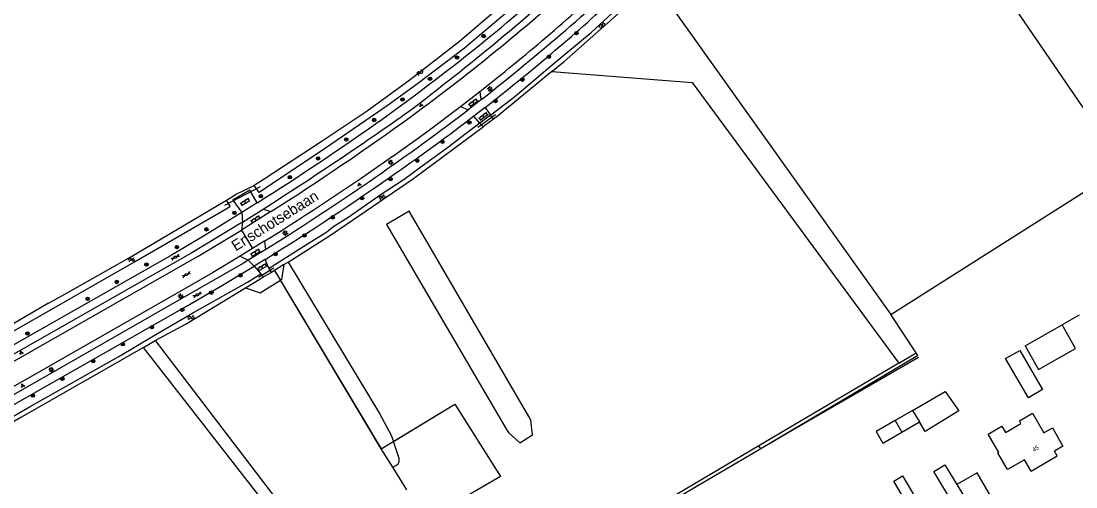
# Model space of a CAD drawing. Extents: x 135999 to 138000, y 396000 to 398501.
# Drawn here: x 136302.3 to 136547.8, y 397723.2 to 397831.7 of the extents above; entities that cross this region are included whole.
import ezdxf

# ---------------------------------------------------------------- set-up
doc = ezdxf.new("R2010")
doc.units = 0
for name, color, linetype in [('gg-afsc-lijn draadraster', 7, 'Continuous'), ('gg-afsc-muur', 7, 'Continuous'), ('gg-anno-huisnummerreeks BGT', 7, 'Continuous'), ('gg-anno-openbare ruimte label', 7, 'Continuous'), ('gg-bbg-bijgebouw', 7, 'Continuous'), ('gg-bbg-gedigitaliseerde bebouwing', 7, 'Continuous'), ('gg-bbg-gedigitaliseerde bijgebouw', 7, 'Continuous'), ('gg-bbg-hoofdgebouw', 7, 'Continuous'), ('gg-bbg-tussenscheiding', 7, 'Continuous'), ('gg-knt-verharding', 7, 'Continuous'), ('gg-kntw-bovenkant insteek waterloop', 7, 'Continuous'), ('gg-kwrk-duiker nz buis', 7, 'Continuous'), ('gt-grn-groengrens', 7, 'Continuous'), ('gt-grn-vlakafsluiter', 7, 'Continuous'), ('gt-grn-weggrens', 7, 'Continuous'), ('gt-symb-boom', 7, 'Continuous'), ('gt-symb-gesloten verharding', 7, 'Continuous'), ('gt-symb-groenvak', 7, 'Continuous'), ('gt-symb-klinker verharding', 7, 'Continuous'), ('gt-symb-lichtmast', 7, 'Continuous'), ('gt-symb-watersymbool', 7, 'Continuous'), ('gx-grn-maaiveld', 7, 'Continuous')]:
    doc.layers.add(name, color=color, linetype=linetype)

# ---------------------------------------------------------------- blocks, each defined once
blk = doc.blocks.new('gt0-BOOM')
at = {"layer": 'gt-symb-boom'}
for radius in [0.4, 0.2]:
    blk.add_circle((0, 0), radius, dxfattribs=at)
blk = doc.blocks.new('gt0-WA')
at = {"layer": 'gt-symb-watersymbool'}
for centre, start, end in [((-0.32, 0.02), 28.0725, 151.9275), ((0.43, 0.42), 208.0725, 331.9275), ((-0.32, -0.43), 28.0725, 151.9275), ((0.43, -0.03), 208.0725, 331.9275)]:
    blk.add_arc(centre, 0.425, start, end, dxfattribs=at)
blk = doc.blocks.new('gt0-GRVAK')
at = {"layer": 'gt-symb-groenvak'}
for p, q in [((-0.11, 0.19), (-0.23, 0.24)), ((-0.18, 0.15), (0.09, 0.15)), ((-0.09, 0.21), (-0.16, 0.32)), ((-0.05, 0.21), (-0.05, 0.39)), ((0, 0.21), (0.06, 0.32)), ((0.02, 0.19), (0.13, 0.24)), ((0.26, -0.05), (0.2, 0.06)), ((0.3, -0.05), (0.3, 0.13)), ((0.35, -0.05), (0.41, 0.06)), ((-0.24, -0.23), (-0.36, -0.18)), ((-0.32, -0.26), (-0.05, -0.26)), ((-0.23, -0.21), (-0.29, -0.1)), ((-0.18, -0.2), (-0.18, -0.02)), ((-0.14, -0.21), (-0.07, -0.1)), ((-0.12, -0.23), (0, -0.18)), ((0.24, -0.07), (0.12, -0.02)), ((0.17, -0.11), (0.44, -0.11)), ((0.37, -0.07), (0.49, -0.02))]:
    blk.add_line(p, q, dxfattribs=at)
blk = doc.blocks.new('gt0-LMAST')
at = {"layer": 'gt-symb-lichtmast'}
for p, q in [((-0.18, 0.17), (-0.45, 0.44)), ((-0.01, 0.25), (-0.01, 0.62)), ((0.17, 0.17), (0.44, 0.44)), ((-0.26, 0), (-0.63, 0)), ((-0.18, -0.18), (-0.45, -0.45)), ((-0.01, -0.25), (-0.01, -0.63)), ((0.44, -0.45), (0.17, -0.18)), ((0.24, 0), (0.62, 0))]:
    blk.add_line(p, q, dxfattribs=at)
blk.add_circle((-0.01, 0), 0.25, dxfattribs=at)
blk = doc.blocks.new('gt0-KL1')
at = {"layer": 'gt-symb-klinker verharding'}
for p, q in [((-1.15, 0.3), (1.15, 0.3)), ((-1, -0.3), (-1, 0.3)), ((-0.5, 0.3), (-0.5, 0.45)), ((0, -0.3), (0, 0.3)), ((0.5, 0.3), (0.5, 0.45)), ((1, -0.3), (1, 0.3)), ((-1.15, -0.3), (1.15, -0.3)), ((-0.5, -0.45), (-0.5, -0.3)), ((0.5, -0.45), (0.5, -0.3))]:
    blk.add_line(p, q, dxfattribs=at)
blk = doc.blocks.new('gt0-GESVH1')
at = {"layer": 'gt-symb-gesloten verharding'}
for p, q in [((-0.99, -0.26), (0.01, 0.24)), ((0.01, -0.26), (-0.99, 0.24)), ((0.01, 0.24), (1.01, -0.26)), ((1.01, 0.24), (0.01, -0.26))]:
    blk.add_line(p, q, dxfattribs=at)

msp = doc.modelspace()

# ---------------------------------------------------------------- linework, layer by layer
at = {"layer": 'gg-afsc-lijn draadraster'}
for points in [[(136361.32, 397773.58), (136386.13, 397732.1), (136403.25, 397742.5), (136413.87, 397725.66), (136396.47, 397715.47), (136406.27, 397699.96)], [(136406.27, 397699.96), (136406.51, 397699.57), (136408.1, 397698.31), (136433.71, 397714.55), (136438.11, 397713.96), (136442.5, 397713.38), (136481.62, 397736.34), (136511.13, 397753.39)]]:
    msp.add_lwpolyline(points, dxfattribs=at)
at = {"layer": 'gg-afsc-muur'}
msp.add_line((136548.54, 397763.19), (136544.57, 397760.93), dxfattribs=at)
at = {"layer": 'gg-bbg-bijgebouw'}
msp.add_line((136535.95, 397756.03), (136544.57, 397760.93), dxfattribs=at)
at = {"layer": 'gg-bbg-gedigitaliseerde bebouwing'}
msp.add_line((136524.79, 397726.5), (136520.05, 397723.74), dxfattribs=at)
for points in [[(136520.73, 397716.72), (136514.72, 397726.81), (136517.3, 397728.34), (136520.05, 397723.74)], [(136509.82, 397716.95), (136505.37, 397724.54), (136507.43, 397725.76), (136510.21, 397721.05)]]:
    msp.add_lwpolyline(points, dxfattribs=at)
at = {"layer": 'gg-bbg-gedigitaliseerde bijgebouw'}
for p, q in [((136509.74, 397741.03), (136505.68, 397738.68)), ((136507.25, 397735.96), (136511.35, 397738.34))]:
    msp.add_line(p, q, dxfattribs=at)
for points in [[(136535.95, 397756.03), (136539.09, 397750.52), (136547.71, 397755.43), (136544.57, 397760.93)], [(136531.42, 397753.08), (136534.74, 397755), (136540.02, 397745.88), (136536.7, 397743.96), (136531.42, 397753.08)], [(136509.74, 397741.03), (136517.36, 397745.45), (136520.52, 397740.94), (136512.68, 397736.1), (136511.35, 397738.34)], [(136505.68, 397738.68), (136501.3, 397736.14), (136502.88, 397733.43), (136507.25, 397735.96)]]:
    msp.add_lwpolyline(points, dxfattribs=at)
at = {"layer": 'gg-bbg-hoofdgebouw'}
msp.add_line((136544.75, 397732.71), (136542.76, 397731.56), dxfattribs=at)
for points in [[(136537.33, 397726.92), (136535.81, 397729.55), (136531.89, 397727.26), (136529.63, 397731.14), (136529.81, 397731.24), (136527.32, 397735.5), (136530.52, 397737.35), (136531.37, 397735.89), (136534.98, 397737.98), (136534.61, 397738.62), (136537.65, 397740.38), (136540.3, 397735.8), (136542.29, 397736.95), (136544.75, 397732.71)], [(136537.33, 397726.92), (136543.41, 397730.43), (136542.76, 397731.56)], [(136527.5, 397711.42), (136532.02, 397714.07), (136524.79, 397726.5)]]:
    msp.add_lwpolyline(points, dxfattribs=at)
at = {"layer": 'gg-bbg-tussenscheiding'}
for p, q in [((136509.74, 397741.03), (136511.35, 397738.34)), ((136505.68, 397738.68), (136507.25, 397735.96))]:
    msp.add_line(p, q, dxfattribs=at)
msp.add_lwpolyline([(136520.05, 397723.74), (136523.37, 397718.29), (136527.5, 397711.42)], dxfattribs=at)
at = {"layer": 'gg-knt-verharding'}
for p, q in [((136404.58, 397811.81), (136409.08, 397815.3)), ((136404.58, 397811.81), (136406.39, 397811.02)), ((136409.52, 397813.46), (136406.39, 397811.02)), ((136410.32, 397811.57), (136407.72, 397809.56)), ((136410.32, 397811.57), (136411.59, 397809.76)), ((136404.03, 397809.21), (136406.39, 397811.02)), ((136409.1, 397807.89), (136407.72, 397809.56)), ((136411.59, 397809.76), (136409.1, 397807.89)), ((136357.26, 397789.32), (136353.67, 397787.08)), ((136360.49, 397787.31), (136353.62, 397783.01)), ((136353.83, 397784.87), (136358.67, 397787.91)), ((136358.67, 397787.91), (136360.49, 397787.31)), ((136353.83, 397784.87), (136353.62, 397783.01)), ((136359.08, 397780.49), (136356.21, 397778.73)), ((136359.27, 397778.52), (136359.08, 397780.49)), ((136356.21, 397778.73), (136353.34, 397776.96)), ((136359.27, 397778.52), (136355.21, 397776.01)), ((136353.34, 397776.96), (136355.21, 397776.01)), ((136359.14, 397776.18), (136356.58, 397774.6)), ((136356.58, 397774.6), (136358.09, 397772.84))]:
    msp.add_line(p, q, dxfattribs=at)
for points in [[(136409.08, 397815.3), (136409.23, 397813.83), (136409.52, 397813.46)], [(136388.75, 397800.17), (136396.73, 397805.91), (136404.58, 397811.81)], [(136357.26, 397789.32), (136355.54, 397792.26), (136351.63, 397789.94), (136353.67, 397787.08)], [(136353.67, 397787.08), (136345.16, 397781.84), (136337.46, 397777.26), (136272.27, 397740.25)], [(136353.83, 397784.87), (136347.97, 397781.25), (136342.07, 397777.68), (136274.54, 397739.3)], [(136277.09, 397739.09), (136343.54, 397776.93), (136348.59, 397779.95), (136353.62, 397783.01)], [(136353.34, 397776.96), (136346.85, 397773.08), (136340.32, 397769.27), (136265.5, 397726.59)], [(136355.21, 397776.01), (136354.09, 397775.33), (136310.77, 397750.44), (136267.58, 397725.81)], [(136270.22, 397725.11), (136340.95, 397765.37), (136348.8, 397769.93), (136356.58, 397774.6)], [(136359.14, 397776.18), (136359.66, 397774.71), (136360.04, 397774.07)]]:
    msp.add_lwpolyline(points, dxfattribs=at)
for centre, radius, start, end in [((136075.08, 398239.48), 541.61, 308.1332, 313.4724), ((136098.79, 398209.98), 493.58, 305.5412, 312.2016), ((136022.19, 398299.22), 613.08, 307.16066, 312.12826), ((136091.37, 398219.85), 509.36, 306.3322, 312.2077), ((136103.81, 398204.54), 494.68, 308.1058, 312.7313), ((136119.37, 398185.54), 473.82, 307.8825, 312.6711), ((135948.26, 398435.74), 766.89, 302.35478, 305.4011), ((136029.19, 398307.97), 623.91, 301.94151, 306.92586), ((136027.61, 398312.06), 621.42, 302.38932, 306.03134), ((136117.94, 398187.42), 476.18, 304.8004, 307.4844), ((136000.23, 398353.5), 667.65, 302.3271, 305.26388), ((136031.52, 398306.61), 619.75, 301.90662, 305.19857), ((136045.24, 398283.82), 596.85, 301.73079, 305.24957)]:
    msp.add_arc(centre, radius, start, end, dxfattribs=at)
at = {"layer": 'gg-kntw-bovenkant insteek waterloop'}
for p, q in [((136412.27, 397808.79), (136411.59, 397809.76)), ((136409.1, 397807.89), (136409.82, 397807.02)), ((136358.92, 397794.87), (136356.56, 397793.36)), ((136358.09, 397772.84), (136358.76, 397772.15)), ((136360.61, 397773.13), (136360.04, 397774.07)), ((136361.32, 397773.58), (136360.61, 397773.13)), ((136380.45, 397692.11), (136330.83, 397755.65))]:
    msp.add_line(p, q, dxfattribs=at)
for points in [[(136411.59, 397809.76), (136417.22, 397814.07), (136425.93, 397821.47), (136435, 397829.02), (136461.6, 397853.58), (136462.35, 397852.78)], [(136427.57, 397847.31), (136420.74, 397840.94), (136404.36, 397826.91), (136392.84, 397817.98), (136382.84, 397810.71), (136372.16, 397803.55), (136358.92, 397794.87)], [(136429.16, 397845.61), (136423.89, 397841.1), (136418.13, 397836.05), (136412.52, 397831.22), (136405.55, 397825.35), (136394.55, 397817.07), (136387.51, 397811.95), (136373.18, 397802.08), (136357.71, 397791.73), (136356.56, 397793.36)], [(136409.1, 397807.89), (136405.93, 397805.52), (136401.57, 397802.16), (136396.51, 397798.53), (136391.45, 397794.8), (136386.11, 397791.25), (136378.4, 397785.86), (136374.85, 397783.65), (136373.52, 397782.51), (136368.17, 397779.22), (136360.04, 397774.07)], [(136257.19, 397736.5), (136257.93, 397735.12), (136271.37, 397742.89), (136299.19, 397758.7), (136328.7, 397775.63), (136350.42, 397788.2), (136351, 397788.57), (136350.11, 397789.97)], [(136308.69, 397765.98), (136311.82, 397767.66), (136327.33, 397776.47), (136350.11, 397789.97)], [(136265.14, 397718.06), (136264.52, 397719.12), (136266.43, 397720.21), (136275.38, 397725.12), (136291.53, 397734.51), (136304.43, 397741.92), (136325.07, 397753.57), (136333.54, 397758.61), (136342.47, 397763.78), (136355.03, 397770.85), (136358.09, 397772.84)], [(136308.69, 397765.98), (136297.51, 397759.41), (136280.73, 397750), (136265.57, 397741.4), (136257.19, 397736.5)], [(136330.83, 397755.65), (136302.27, 397739.35), (136289.12, 397731.76), (136275.77, 397724.21), (136265.14, 397718.06)]]:
    msp.add_lwpolyline(points, dxfattribs=at)
at = {"layer": 'gg-kwrk-duiker nz buis'}
for p, q in [((136412.73, 397809.87), (136408.65, 397806.86)), ((136357.95, 397793.06), (136349.71, 397788.74)), ((136361.18, 397774.12), (136357.57, 397771.95))]:
    msp.add_line(p, q, dxfattribs=at)
at = {"layer": 'gt-grn-groengrens'}
for p, q in [((136352.41, 397791.37), (136356.56, 397793.36)), ((136350.11, 397789.97), (136352.41, 397791.37))]:
    msp.add_line(p, q, dxfattribs=at)
at = {"layer": 'gt-grn-vlakafsluiter'}
msp.add_line((136330.83, 397755.65), (136333.58, 397757.3), dxfattribs=at)
at = {"layer": 'gt-grn-weggrens'}
for p, q in [((136412.27, 397808.79), (136409.82, 397807.02)), ((136353.67, 397787.08), (136353.83, 397784.87)), ((136353.62, 397783.01), (136356.21, 397778.73)), ((136355.21, 397776.01), (136356.58, 397774.6)), ((136360.61, 397773.13), (136358.76, 397772.15))]:
    msp.add_line(p, q, dxfattribs=at)
at = {"layer": 'gx-grn-maaiveld'}
for p, q in [((136558.84, 397797.71), (136498.12, 397886.85)), ((136449.57, 397840.8), (136504.69, 397763.39)), ((136504.69, 397763.39), (136552.61, 397793.8)), ((136363.51, 397774.96), (136361.32, 397773.58)), ((136363.51, 397774.96), (136364.45, 397775.56)), ((136510.61, 397754.41), (136504.69, 397763.39)), ((136333.58, 397757.3), (136370.6, 397708.73)), ((136506.59, 397752.03), (136510.61, 397754.41)), ((136506.59, 397752.03), (136474.03, 397732.77)), ((136392.12, 397722.52), (136388.87, 397727.8))]:
    msp.add_line(p, q, dxfattribs=at)
for points in [[(136425.82, 397819.89), (136428.7, 397822.26), (136448.86, 397840.14), (136449.57, 397840.8)], [(136425.82, 397819.89), (136413.12, 397809.41), (136412.27, 397808.79)], [(136425.82, 397819.89), (136458.49, 397817.38), (136506.59, 397752.03)], [(136364.45, 397775.56), (136374.58, 397781.97), (136393.63, 397795.02), (136409.82, 397807.02)], [(136420.52, 397739.63), (136392.61, 397787.39), (136387.36, 397784.32), (136415.27, 397736.57), (136415.78, 397735.92), (136418.36, 397733.48), (136421.37, 397735.36), (136420.91, 397738.77), (136420.52, 397739.63)], [(136363.51, 397774.96), (136362.95, 397771.49), (136362.67, 397771.32)], [(136364.45, 397775.56), (136385.7, 397740.3), (136388.47, 397735.27), (136388.97, 397733.82)], [(136354.59, 397769.57), (136356.35, 397770.64), (136358.76, 397772.15)], [(136354.59, 397769.57), (136357.99, 397768.38), (136362.67, 397771.32)], [(136388.87, 397727.8), (136386.13, 397732.1), (136362.67, 397771.32)], [(136333.58, 397757.3), (136340.78, 397761.2), (136354.59, 397769.57)], [(136510.61, 397754.41), (136510.92, 397753.74), (136474.45, 397732.09), (136474.03, 397732.77)], [(136388.97, 397733.82), (136403.25, 397742.5), (136413.87, 397725.66), (136396.47, 397715.47)], [(136388.87, 397727.8), (136390.06, 397728.53), (136390.33, 397729.12), (136390.33, 397729.85), (136388.97, 397733.82)], [(136474.03, 397732.77), (136441.49, 397713.53), (136438.11, 397713.96), (136433.71, 397714.55), (136408.1, 397698.31), (136406.51, 397699.57), (136406.27, 397699.96)]]:
    msp.add_lwpolyline(points, dxfattribs=at)

# ---------------------------------------------------------------- block references
at = {"layer": 'gt-symb-boom'}
for p in [(136409.98, 397828.18), (136431.55, 397828.86), (136425.16, 397823.35), (136403.77, 397823.16), (136397.49, 397818.24), (136418.97, 397818.02), (136391.1, 397813.41), (136412.74, 397813.05), (136384.49, 397808.62), (136406.63, 397808.03), (136378.02, 397804.1), (136400.37, 397803.58), (136371.45, 397799.68), (136394.52, 397799.17), (136364.87, 397795.31), (136388.3, 397794.88), (136358.13, 397790.88), (136381.67, 397790.45), (136351.98, 397787.01), (136374.84, 397785.96), (136345.46, 397783.17), (136368.29, 397781.75), (136338.6, 397779.04), (136361.55, 397777.42), (136331.52, 397775), (136353.39, 397772.46), (136324.61, 397770.92), (136317.83, 397767.01), (136346.62, 397768.44), (136339.86, 397764.43), (136332.78, 397760.39), (136303.83, 397758.94), (136326.01, 397756.42), (136319.13, 397752.5), (136311.95, 397748.4), (136305.08, 397744.48)]:
    msp.add_blockref('gt0-BOOM', p, dxfattribs=at)
at = {"layer": 'gt-symb-gesloten verharding'}
for p, rotation in [((136338.26, 397776.69), -150.7171714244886), ((136340.81, 397772.62), -150.71717142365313), ((136343.35, 397767.93), -150.7171714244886)]:
    msp.add_blockref('gt0-GESVH1', p, dxfattribs=dict(at, rotation=rotation))
at = {"layer": 'gt-symb-groenvak'}
for p in [(136395.41, 397812.11), (136381.05, 397793.63), (136302.39, 397754.44), (136302.71, 397746.79)]:
    msp.add_blockref('gt0-GRVAK', p, dxfattribs=at)
at = {"layer": 'gt-symb-klinker verharding'}
for p, rotation in [((136407.57, 397812.7), 37.80965212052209), ((136409.91, 397809.51), 37.80965211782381), ((136354.45, 397789.56), 31.13079914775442), ((136356.91, 397785.54), 31.798912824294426), ((136356.89, 397777.74), 31.798912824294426), ((136358.44, 397774.36), 31.798912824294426)]:
    msp.add_blockref('gt0-KL1', p, dxfattribs=dict(at, rotation=rotation))
at = {"layer": 'gt-symb-lichtmast'}
for p in [(136411.44, 397815.85), (136388.35, 397798.76), (136363.83, 397782.31), (136339.48, 397767.6), (136309.4, 397750.49)]:
    msp.add_blockref('gt0-LMAST', p, dxfattribs=at)
at = {"layer": 'gt-symb-watersymbool'}
for p, rotation in [((136437.46, 397830.62), 54.642057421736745), ((136395.1, 397819.64), 47.91906958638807), ((136386.28, 397790.62), 41.8381492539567), ((136327.99, 397776.06), 30.206934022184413), ((136341.82, 397762.61), 30.206934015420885)]:
    msp.add_blockref('gt0-WA', p, dxfattribs=dict(at, rotation=rotation))

# ---------------------------------------------------------------- texts
at = {"layer": 'gg-anno-huisnummerreeks BGT'}
msp.add_text('45', height=1, rotation=29.9, dxfattribs=at).set_placement((136537.96, 397731.33))
at = {"layer": 'gg-anno-openbare ruimte label'}
msp.add_text('Enschotsebaan', height=2.5, rotation=32.1, dxfattribs=at).set_placement((136352.29, 397778.01))

doc.saveas('drawing.dxf')
